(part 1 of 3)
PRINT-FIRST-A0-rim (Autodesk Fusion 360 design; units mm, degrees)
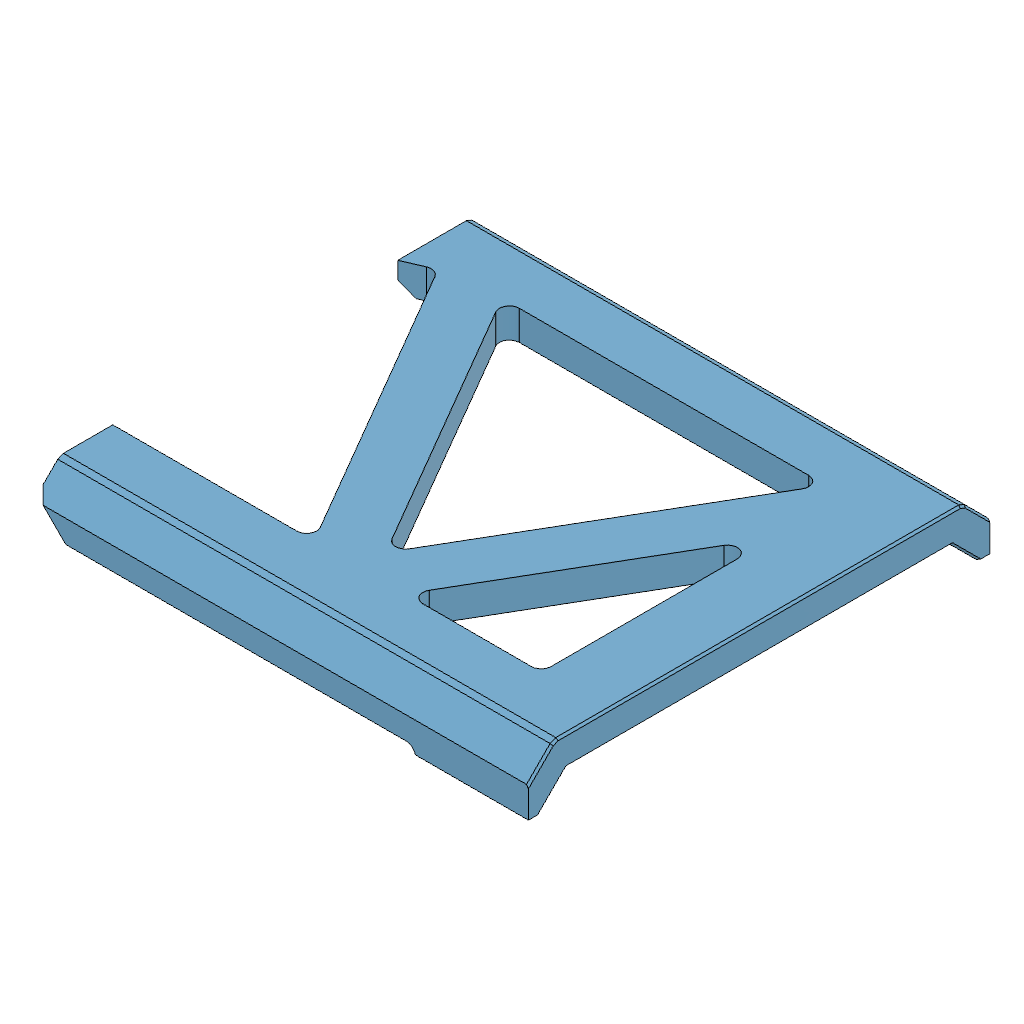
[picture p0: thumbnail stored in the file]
part number: 2026-11-02-20-17-55-344
part number: 2026-11-02-20-17-59-218
part number: 2026-11-02-20-17-59-224
part number: 2026-11-02-20-19-00-695
part number: 2026-11-02-20-19-03-009
part number: 2026-11-02-20-19-04-949
part number: 2026-11-02-20-19-06-912
part number: 2026-11-02-20-19-11-903
part number: 2026-11-02-20-19-12-666
part number: 2026-11-02-20-19-12-978
part number: 2026-11-02-20-19-13-740
part number: 2026-11-02-20-19-14-532
part number: 2026-11-02-20-19-15-361
part number: 2026-11-02-20-19-17-468
part number: 2026-11-02-20-19-19-583
part number: 2026-11-02-20-19-25-638
part number: 2026-11-02-20-19-39-091
parameter "bodyWidth" = 150 comment "Regular octagon across flats; corner diameter is larger."
parameter "bodyLength" = 260 comment "Overall straight length of the shared master blank."
parameter "splitAngle" = 45 comment "Keep this lesson angle at45 degrees."
parameter "faceGap" = 1 comment "Gap between the two printed joint faces."
parameter "wall" = 4.5 comment "Integrated shell and side brace radial thickness."
parameter "faceHalfWidth" = 31.066 (= "bodyWidth * ( sqrt(2) - 1 ) / 2") comment "Half-width of each outer planar facet."
parameter "memberWidth" = 8 comment "Nominal brace and corner chord width in a facet."
parameter "nodeHalfWidth" = 27.066 (= "faceHalfWidth - memberWidth / 2") comment "Chord centerlines measured from facet center."
parameter "jointNodeQ" = 7 comment "First truss skeleton row from the center joint plane."
parameter "endRim" = 10 comment "Uncut axial rim at each distant end."
parameter "endNodeX" = 124 (= "bodyLength / 2 - endRim + memberWidth / 2") comment "Last skeleton row before aperture inset."
parameter "apertureRadius" = 1.5 comment "Rounded internal corners at triangular openings."
parameter "spokeWidth" = 10 comment "Width of each deep bearing bulkhead spoke."
parameter "spokeDepth" = 18 comment "Bulkhead depth normal to the diagonal joint face."
parameter "carrierOD" = 52 comment "Outside of integrated A front bearing carrier."
parameter "rearCarrierClearance" = 46 comment "Internal carrier relief above front bearing shoulder."
parameter "tubeCornerChamfer" = 0.5 comment "Exposed outside octagon corner bevel."
parameter "tubeRimChamfer" = 0.3 comment "End rim and print-contact edge relief."
parameter "cordStation" = 125 (= "bodyLength / 2 - endRim / 2") comment "Load-test cord port center measured along body X."
parameter "bearingOD" = 22 comment "608 measured outside diameter."
parameter "bearingID" = 8 comment "608 bore."
parameter "bearingWidth" = 7 comment "608 width."
parameter "seatAllowance" = 0.2 comment "Trial DIAMETRAL clearance; choose with printed coupon."
parameter "seatDiameter" = 22.2 (= "bearingOD + seatAllowance") comment "Measured fit controls this."
parameter "coreOD" = 44 comment "Bearing holder outer diameter."
parameter "raceRelief" = 19.5 comment "Outer-ring shoulder opening; verify seals."
parameter "frontSeatDepth" = 7.1 comment "0.1 mm outer-ring axial allowance."
parameter "rearSeatDepth" = 7.2 comment "0.2 mm outer-ring axial float."
parameter "shoulder" = 3 comment "Backing behind each bearing seat."
parameter "supportSpacer" = 12 comment "Purchased metal M3 spacer length."
parameter "supportCircle" = 34 comment "Three M3 support bolts."
parameter "supportSpacerOD" = 6 comment "Purchased spacer outside diameter."
parameter "capThickness" = 3 comment "Both printed outer-ring retaining caps."
parameter "m3Clearance" = 3.3 comment "M3 through holes."
parameter "m4Clearance" = 4.3 comment "M4 through holes."
parameter "qFront" = 0.5 (= "faceGap / 2") comment "Front bearing starts at A mating face."
parameter "qFrontBack" = 10.6 (= "qFront + frontSeatDepth + shoulder") comment "End of integrated A holder."
parameter "qRearBase" = 22.6 (= "qFrontBack + supportSpacer") comment "Start of removable rear holder."
parameter "qRearBearing" = 25.6 (= "qRearBase + shoulder") comment "Rear bearing inner end."
parameter "qRearEnd" = 32.8 (= "qRearBearing + rearSeatDepth") comment "Rear holder outer end."
parameter "bearingSpacing" = 25.1 (= "qRearBearing - qFront") comment "Derived support-center spacing, not a bearing rating."
parameter "mountOD" = 76 comment "B mount and F flange outside diameter."
parameter "mountCircle" = 64 comment "Four M4 attachment holes."
parameter "mountOpening" = 50.3 comment "B through opening."
parameter "hubFace" = -23 comment "Metal hub flat mounting face."
parameter "adapterThickness" = 6 comment "F flange and metal compression sleeve length."
parameter "pilotDiameter" = 50 comment "F shallow centering pilot."
parameter "pilotInside" = 34 comment "Clearance around metal hub."
parameter "pilotHeight" = 2 comment "Short pilot only."
parameter "hubHoleSpacing" = 16 comment "Metal Sonic hub square hole spacing."
parameter "sleeveOD" = 8 comment "M4 metal compression sleeves."
parameter "sleeveAllowance" = 0.2 comment "Trial DIAMETRAL sleeve clearance."
parameter "shaftClearance" = 8.5 comment "F clearance hole; not a bearing."
parameter "nutAF" = 7.2 comment "M4 nominal 7 AF nut trial pocket."
parameter "nutDepth" = 4 comment "Open front M4 nut pocket."
parameter "rootRadius" = 1 comment "Hub-to-wall blend."
parameter "entryChamfer" = 0.4 comment "Assembly lead-in."
parameter "bedRelief" = 0.3 comment "Bed-contact edge allowance."
parameter "driverPort" = 5 comment "Clearance for bare3 mm hex-key shafts; bulky bit holders do not fit."
parameter "accessPadWidth" = 12 comment "Reinforced access-port capsule width."
parameter "accessPadExtra" = 2 comment "Local inward reinforcement beyond nominal side wall."
sketch "01 Master Octagon" plane through (0, 0, 0) normal (1, 0, 0) x axis (0, 0, -1)
  line L1 (31.066, 75) -> (75, 31.066)
  line L2 (-31.066, 75) -> (31.066, 75)
  line L3 (-75, 31.066) -> (-31.066, 75)
  line L4 (-75, -31.066) -> (-75, 31.066)
  line L5 (-31.066, -75) -> (-75, -31.066)
  line L6 (31.066, -75) -> (-31.066, -75)
  line L7 (75, -31.066) -> (31.066, -75)
  line L8 (75, 31.066) -> (75, -31.066)
  point P1 (0, 0)
  point P10 (0, 0)
  point P3 (31.066, 75)
  point P8 (31.066, -75)
  coincident P1 P10
  horizontal L2
  dimension "d59" distance P3 P8 = 150 (= "bodyWidth")
extrude "Extrude1" new body sketch "01 Master Octagon" distance 260 (= "bodyLength")
work_plane "WorkPlane1" RotateAngle 45 (= "splitAngle") ExtraOffset 0
split "Split1"
offset_faces "OffsetFaces1" distance -0.5 (= "-faceGap / 2")
offset_faces "OffsetFaces2" distance -0.5 (= "-faceGap / 2")
component_from_bodies "Body->Comp1"
component_from_bodies "Body->Comp2"
shell "Shell1" innerThickness 4.5 (= "wall")
shell "Shell1" innerThickness 4.5 (= "wall")
work_plane "WorkPlane1" RotateAngle -90 ExtraOffset 0
work_plane "WorkPlane2" AlongDistance 75 (= "bodyWidth / 2") ExtraOffset 0
sketch "A Facet 0 Triangle 1" plane through (0, 75, 0) normal (0, 1, 0) x axis (1, 0, 0)
  line L1 (-65.1005, -27.066) -> (-65.1005, 27.066)
  line L2 (60.9665, 27.066) -> (-65.1005, -27.066)
  line L3 (-65.1005, 27.066) -> (60.9665, 27.066)
  line L4 (-61.1005, -20.9953) -> (-61.1005, 23.066)
  line L5 (41.513, 23.066) -> (-61.1005, -20.9953)
  line L6 (-61.1005, 23.066) -> (41.513, 23.066)
  point P1 (0, 0)
  point P2 (-65.1005, 27.066)
  point P3 (-65.1005, -27.066)
  point P4 (60.9665, 27.066)
  dimension "d72" distance P1 P2 = 65.1005 (= "Linear Dimension-2")
  dimension "d73" distance P1 P2 = 27.066 (= "Linear Dimension-3")
  dimension "d74" distance P1 P3 = 65.1005 (= "Linear Dimension-4")
  dimension "d75" distance P1 P3 = 27.066 (= "Linear Dimension-5")
  dimension "d76" distance P1 P4 = 60.9665 (= "Linear Dimension-6")
  dimension "d77" distance P1 P4 = 27.066 (= "Linear Dimension-7")
  dimension "d78" = -4 (= "-memberWidth / 2")
extrude "Extrude1" cut sketch "A Facet 0 Triangle 1" profile of L5 L6 L4 against normal blind 4.7 (magnitude of "-( wall + 0.2 mm )")
sketch "A Facet 0 Triangle 2" plane through (0, 75, 0) normal (0, 1, 0) x axis (1, 0, 0)
  line L1 (60.9665, 27.066) -> (-65.1005, -27.066)
  line L2 (92.4832, -27.066) -> (60.9665, 27.066)
  line L3 (-65.1005, -27.066) -> (92.4832, -27.066)
  line L4 (59.2912, 21.9935) -> (-45.647, -23.066)
  line L5 (85.5258, -23.066) -> (59.2912, 21.9935)
  line L6 (-45.647, -23.066) -> (85.5258, -23.066)
  point P1 (0, 0)
  point P2 (-65.1005, -27.066)
  point P3 (60.9665, 27.066)
  point P4 (92.4832, -27.066)
  dimension "d81" distance P1 P2 = 65.1005 (= "Linear Dimension-2")
  dimension "d82" distance P1 P2 = 27.066 (= "Linear Dimension-3")
  dimension "d83" distance P1 P3 = 60.9665 (= "Linear Dimension-4")
  dimension "d84" distance P1 P3 = 27.066 (= "Linear Dimension-5")
  dimension "d85" distance P1 P4 = 92.4832 (= "Linear Dimension-6")
  dimension "d86" distance P1 P4 = 27.066 (= "Linear Dimension-7")
  dimension "d87" = 4 (= "memberWidth / 2")
extrude "Extrude2" cut sketch "A Facet 0 Triangle 2" profile of L5 L6 L4 against normal blind 4.7 (magnitude of "-( wall + 0.2 mm )")
sketch "A Facet 0 Triangle 3" plane through (0, 75, 0) normal (0, 1, 0) x axis (1, 0, 0)
  line L1 (92.4832, -27.066) -> (60.9665, 27.066)
  line L2 (124, 27.066) -> (92.4832, -27.066)
  line L3 (60.9665, 27.066) -> (124, 27.066)
  line L4 (92.4832, -19.1161) -> (67.924, 23.066)
  line L5 (117.0425, 23.066) -> (92.4832, -19.1161)
  line L6 (67.924, 23.066) -> (117.0425, 23.066)
  point P1 (0, 0)
  point P2 (60.9665, 27.066)
  point P3 (92.4832, -27.066)
  point P4 (124, 27.066)
  dimension "d90" distance P1 P2 = 60.9665 (= "Linear Dimension-2")
  dimension "d91" distance P1 P2 = 27.066 (= "Linear Dimension-3")
  dimension "d92" distance P1 P3 = 92.4832 (= "Linear Dimension-4")
  dimension "d93" distance P1 P3 = 27.066 (= "Linear Dimension-5")
  dimension "d94" distance P1 P4 = 124 (= "Linear Dimension-6")
  dimension "d95" distance P1 P4 = 27.066 (= "Linear Dimension-7")
  dimension "d96" = -4 (= "-memberWidth / 2")
extrude "Extrude3" cut sketch "A Facet 0 Triangle 3" profile of L5 L6 L4 against normal blind 4.7 (magnitude of "-( wall + 0.2 mm )")
sketch "A Facet 0 Triangle 4" plane through (0, 75, 0) normal (0, 1, 0) x axis (1, 0, 0)
  line L1 (124, 27.066) -> (92.4832, -27.066)
  line L2 (124, -27.066) -> (124, 27.066)
  line L3 (92.4832, -27.066) -> (124, -27.066)
  line L4 (120, 12.2459) -> (99.4407, -23.066)
  line L5 (120, -23.066) -> (120, 12.2459)
  line L6 (99.4407, -23.066) -> (120, -23.066)
  point P1 (0, 0)
  point P2 (92.4832, -27.066)
  point P3 (124, 27.066)
  point P4 (124, -27.066)
  dimension "d99" distance P1 P2 = 92.4832 (= "Linear Dimension-2")
  dimension "d100" distance P1 P2 = 27.066 (= "Linear Dimension-3")
  dimension "d101" distance P1 P3 = 124 (= "Linear Dimension-4")
  dimension "d102" distance P1 P3 = 27.066 (= "Linear Dimension-5")
  dimension "d103" distance P1 P4 = 124 (= "Linear Dimension-6")
  dimension "d104" distance P1 P4 = 27.066 (= "Linear Dimension-7")
  dimension "d105" = 4 (= "memberWidth / 2")
extrude "Extrude4" cut sketch "A Facet 0 Triangle 4" profile of L5 L6 L4 against normal blind 4.7 (magnitude of "-( wall + 0.2 mm )")
fillet "Fillet1" radius 1.5 (= "apertureRadius")
work_plane "WorkPlane3" RotateAngle -45 ExtraOffset 0
work_plane "WorkPlane4" AlongDistance 75 (= "bodyWidth / 2") ExtraOffset 0
sketch "A Facet 45 Triangle 1" plane through (0, 53.033, 53.033) normal (0, 0.7071, 0.7071) x axis (1, 0, 0)
  line L1 (-23.9949, -27.066) -> (-62.2721, 27.066)
  line L2 (-0.1814, 27.066) -> (-23.9949, -27.066)
  line L3 (-62.2721, 27.066) -> (-0.1814, 27.066)
  line L4 (-24.81, -18.9852) -> (-54.5447, 23.066)
  line L5 (-6.311, 23.066) -> (-24.81, -18.9852)
  line L6 (-54.5447, 23.066) -> (-6.311, 23.066)
  point P1 (0, 0)
  point P2 (-62.2721, 27.066)
  point P3 (-23.9949, -27.066)
  point P4 (-0.1814, 27.066)
  dimension "d114" distance P1 P2 = 62.2721 (= "Linear Dimension-2")
  dimension "d115" distance P1 P2 = 27.066 (= "Linear Dimension-3")
  dimension "d116" distance P1 P3 = 23.9949 (= "Linear Dimension-4")
  dimension "d117" distance P1 P3 = 27.066 (= "Linear Dimension-5")
  dimension "d118" distance P1 P4 = 0.1814 (= "Linear Dimension-6")
  dimension "d119" distance P1 P4 = 27.066 (= "Linear Dimension-7")
  dimension "d120" = -4 (= "-memberWidth / 2")
extrude "Extrude5" cut sketch "A Facet 45 Triangle 1" profile of L5 L6 L4 against normal blind 4.7 (magnitude of "-( wall + 0.2 mm )")
sketch "A Facet 45 Triangle 2" plane through (0, 53.033, 53.033) normal (0, 0.7071, 0.7071) x axis (1, 0, 0)
  line L1 (-0.1814, 27.066) -> (-23.9949, -27.066)
  line L2 (74.6684, -27.066) -> (-0.1814, 27.066)
  line L3 (-23.9949, -27.066) -> (74.6684, -27.066)
  line L4 (1.4863, 20.9235) -> (-17.8653, -23.066)
  line L5 (62.3117, -23.066) -> (1.4863, 20.9235)
  line L6 (-17.8653, -23.066) -> (62.3117, -23.066)
  point P1 (0, 0)
  point P2 (-23.9949, -27.066)
  point P3 (-0.1814, 27.066)
  point P4 (74.6684, -27.066)
  dimension "d123" distance P1 P2 = 23.9949 (= "Linear Dimension-2")
  dimension "d124" distance P1 P2 = 27.066 (= "Linear Dimension-3")
  dimension "d125" distance P1 P3 = 0.1814 (= "Linear Dimension-4")
  dimension "d126" distance P1 P3 = 27.066 (= "Linear Dimension-5")
  dimension "d127" distance P1 P4 = 74.6684 (= "Linear Dimension-6")
  dimension "d128" distance P1 P4 = 27.066 (= "Linear Dimension-7")
  dimension "d129" = 4 (= "memberWidth / 2")
extrude "Extrude6" cut sketch "A Facet 45 Triangle 2" profile of L5 L6 L4 against normal blind 4.7 (magnitude of "-( wall + 0.2 mm )")
sketch "A Facet 45 Triangle 3" plane through (0, 53.033, 53.033) normal (0, 0.7071, 0.7071) x axis (1, 0, 0)
  line L1 (74.6684, -27.066) -> (-0.1814, 27.066)
  line L2 (124, 27.066) -> (74.6684, -27.066)
  line L3 (-0.1814, 27.066) -> (124, 27.066)
  line L4 (74.1179, -21.7315) -> (12.1753, 23.066)
  line L5 (114.9429, 23.066) -> (74.1179, -21.7315)
  line L6 (12.1753, 23.066) -> (114.9429, 23.066)
  point P1 (0, 0)
  point P2 (-0.1814, 27.066)
  point P3 (74.6684, -27.066)
  point P4 (124, 27.066)
  dimension "d132" distance P1 P2 = 0.1814 (= "Linear Dimension-2")
  dimension "d133" distance P1 P2 = 27.066 (= "Linear Dimension-3")
  dimension "d134" distance P1 P3 = 74.6684 (= "Linear Dimension-4")
  dimension "d135" distance P1 P3 = 27.066 (= "Linear Dimension-5")
  dimension "d136" distance P1 P4 = 124 (= "Linear Dimension-6")
  dimension "d137" distance P1 P4 = 27.066 (= "Linear Dimension-7")
  dimension "d138" = -4 (= "-memberWidth / 2")
extrude "Extrude7" cut sketch "A Facet 45 Triangle 3" profile of L5 L6 L4 against normal blind 4.7 (magnitude of "-( wall + 0.2 mm )")
sketch "A Facet 45 Triangle 4" plane through (0, 53.033, 53.033) normal (0, 0.7071, 0.7071) x axis (1, 0, 0)
  line L1 (124, 27.066) -> (74.6684, -27.066)
  line L2 (124, -27.066) -> (124, 27.066)
  line L3 (74.6684, -27.066) -> (124, -27.066)
  line L4 (120, 16.7383) -> (83.7255, -23.066)
  line L5 (120, -23.066) -> (120, 16.7383)
  line L6 (83.7255, -23.066) -> (120, -23.066)
  point P1 (0, 0)
  point P2 (74.6684, -27.066)
  point P3 (124, 27.066)
  point P4 (124, -27.066)
  dimension "d141" distance P1 P2 = 74.6684 (= "Linear Dimension-2")
  dimension "d142" distance P1 P2 = 27.066 (= "Linear Dimension-3")
  dimension "d143" distance P1 P3 = 124 (= "Linear Dimension-4")
  dimension "d144" distance P1 P3 = 27.066 (= "Linear Dimension-5")
  dimension "d145" distance P1 P4 = 124 (= "Linear Dimension-6")
  dimension "d146" distance P1 P4 = 27.066 (= "Linear Dimension-7")
  dimension "d147" = 4 (= "memberWidth / 2")
extrude "Extrude8" cut sketch "A Facet 45 Triangle 4" profile of L5 L6 L4 against normal blind 4.7 (magnitude of "-( wall + 0.2 mm )")
fillet "Fillet2" radius 1.5 (= "apertureRadius")
work_plane "WorkPlane5" RotateAngle 0 ExtraOffset 0
work_plane "WorkPlane6" AlongDistance 75 (= "bodyWidth / 2") ExtraOffset 0
sketch "A Facet 90 Triangle 1" plane through (0, 0, 75) normal (0, 0, 1) x axis (1, 0, 0)
  line L1 (36.9655, -27.066) -> (-17.1665, 27.066)
  line L2 (53.4167, 27.066) -> (36.9655, -27.066)
  line L3 (-17.1665, 27.066) -> (53.4167, 27.066)
  line L4 (35.0777, -19.5214) -> (-7.5097, 23.066)
  line L5 (48.0205, 23.066) -> (35.0777, -19.5214)
  line L6 (-7.5097, 23.066) -> (48.0205, 23.066)
  point P1 (0, 0)
  point P2 (-17.1665, 27.066)
  point P3 (36.9655, -27.066)
  point P4 (53.4167, 27.066)
  dimension "d156" distance P1 P2 = 17.1665 (= "Linear Dimension-2")
  dimension "d157" distance P1 P2 = 27.066 (= "Linear Dimension-3")
  dimension "d158" distance P1 P3 = 36.9655 (= "Linear Dimension-4")
  dimension "d159" distance P1 P3 = 27.066 (= "Linear Dimension-5")
  dimension "d160" distance P1 P4 = 53.4167 (= "Linear Dimension-6")
  dimension "d161" distance P1 P4 = 27.066 (= "Linear Dimension-7")
  dimension "d162" = -4 (= "-memberWidth / 2")
extrude "Extrude9" cut sketch "A Facet 90 Triangle 1" profile of L5 L6 L4 against normal blind 4.7 (magnitude of "-( wall + 0.2 mm )")
sketch "A Facet 90 Triangle 2" plane through (0, 0, 75) normal (0, 0, 1) x axis (1, 0, 0)
  line L1 (53.4167, 27.066) -> (36.9655, -27.066)
  line L2 (124, -27.066) -> (53.4167, 27.066)
  line L3 (36.9655, -27.066) -> (124, -27.066)
  line L4 (55.5648, 20.3777) -> (42.3618, -23.066)
  line L5 (112.2115, -23.066) -> (55.5648, 20.3777)
  line L6 (42.3618, -23.066) -> (112.2115, -23.066)
  point P1 (0, 0)
  point P2 (36.9655, -27.066)
  point P3 (53.4167, 27.066)
  point P4 (124, -27.066)
  dimension "d165" distance P1 P2 = 36.9655 (= "Linear Dimension-2")
  dimension "d166" distance P1 P2 = 27.066 (= "Linear Dimension-3")
  dimension "d167" distance P1 P3 = 53.4167 (= "Linear Dimension-4")
  dimension "d168" distance P1 P3 = 27.066 (= "Linear Dimension-5")
  dimension "d169" distance P1 P4 = 124 (= "Linear Dimension-6")
  dimension "d170" distance P1 P4 = 27.066 (= "Linear Dimension-7")
  dimension "d171" = 4 (= "memberWidth / 2")
extrude "Extrude10" cut sketch "A Facet 90 Triangle 2" profile of L5 L6 L4 against normal blind 4.7 (magnitude of "-( wall + 0.2 mm )")
sketch "A Facet 90 Triangle 3" plane through (0, 0, 75) normal (0, 0, 1) x axis (1, 0, 0)
  line L1 (124, -27.066) -> (53.4167, 27.066)
  line L2 (124, 27.066) -> (124, -27.066)
  line L3 (53.4167, 27.066) -> (124, 27.066)
  line L4 (120, -18.9574) -> (65.2053, 23.066)
  line L5 (120, 23.066) -> (120, -18.9574)
  line L6 (65.2053, 23.066) -> (120, 23.066)
  point P1 (0, 0)
  point P2 (53.4167, 27.066)
  point P3 (124, -27.066)
  point P4 (124, 27.066)
  dimension "d174" distance P1 P2 = 53.4167 (= "Linear Dimension-2")
  dimension "d175" distance P1 P2 = 27.066 (= "Linear Dimension-3")
  dimension "d176" distance P1 P3 = 124 (= "Linear Dimension-4")
  dimension "d177" distance P1 P3 = 27.066 (= "Linear Dimension-5")
  dimension "d178" distance P1 P4 = 124 (= "Linear Dimension-6")
  dimension "d179" distance P1 P4 = 27.066 (= "Linear Dimension-7")
  dimension "d180" = -4 (= "-memberWidth / 2")
extrude "Extrude11" cut sketch "A Facet 90 Triangle 3" profile of L5 L6 L4 against normal blind 4.7 (magnitude of "-( wall + 0.2 mm )")
fillet "Fillet3" radius 1.5 (= "apertureRadius")
work_plane "WorkPlane7" RotateAngle 45 ExtraOffset 0
work_plane "WorkPlane8" AlongDistance 75 (= "bodyWidth / 2") ExtraOffset 0
sketch "A Facet 135 Triangle 1" plane through (0, -53.033, 53.033) normal (0, -0.7071, 0.7071) x axis (1, 0, 0)
  line L1 (82.0711, -27.066) -> (43.7939, 27.066)
  line L2 (124, 27.066) -> (82.0711, -27.066)
  line L3 (43.7939, 27.066) -> (124, 27.066)
  line L4 (82.2175, -20.3449) -> (51.5213, 23.066)
  line L5 (115.8422, 23.066) -> (82.2175, -20.3449)
  line L6 (51.5213, 23.066) -> (115.8422, 23.066)
  point P1 (0, 0)
  point P2 (43.7939, 27.066)
  point P3 (82.0711, -27.066)
  point P4 (124, 27.066)
  dimension "d189" distance P1 P2 = 43.7939 (= "Linear Dimension-2")
  dimension "d190" distance P1 P2 = 27.066 (= "Linear Dimension-3")
  dimension "d191" distance P1 P3 = 82.0711 (= "Linear Dimension-4")
  dimension "d192" distance P1 P3 = 27.066 (= "Linear Dimension-5")
  dimension "d193" distance P1 P4 = 124 (= "Linear Dimension-6")
  dimension "d194" distance P1 P4 = 27.066 (= "Linear Dimension-7")
  dimension "d195" = -4 (= "-memberWidth / 2")
extrude "Extrude12" cut sketch "A Facet 135 Triangle 1" profile of L5 L6 L4 against normal blind 4.7 (magnitude of "-( wall + 0.2 mm )")
sketch "A Facet 135 Triangle 2" plane through (0, -53.033, 53.033) normal (0, -0.7071, 0.7071) x axis (1, 0, 0)
  line L1 (124, 27.066) -> (82.0711, -27.066)
  line L2 (124, -27.066) -> (124, 27.066)
  line L3 (82.0711, -27.066) -> (124, -27.066)
  line L4 (120, 15.3697) -> (90.2289, -23.066)
  line L5 (120, -23.066) -> (120, 15.3697)
  line L6 (90.2289, -23.066) -> (120, -23.066)
  point P1 (0, 0)
  point P2 (82.0711, -27.066)
  point P3 (124, 27.066)
  point P4 (124, -27.066)
  dimension "d198" distance P1 P2 = 82.0711 (= "Linear Dimension-2")
  dimension "d199" distance P1 P2 = 27.066 (= "Linear Dimension-3")
  dimension "d200" distance P1 P3 = 124 (= "Linear Dimension-4")
  dimension "d201" distance P1 P3 = 27.066 (= "Linear Dimension-5")
  dimension "d202" distance P1 P4 = 124 (= "Linear Dimension-6")
  dimension "d203" distance P1 P4 = 27.066 (= "Linear Dimension-7")
  dimension "d204" = 4 (= "memberWidth / 2")
extrude "Extrude13" cut sketch "A Facet 135 Triangle 2" profile of L5 L6 L4 against normal blind 4.7 (magnitude of "-( wall + 0.2 mm )")
fillet "Fillet4" radius 1.5 (= "apertureRadius")
work_plane "WorkPlane9" RotateAngle 90 ExtraOffset 0
work_plane "WorkPlane10" AlongDistance 75 (= "bodyWidth / 2") ExtraOffset 0
sketch "A Facet 180 Triangle 1" plane through (0, -75, 0) normal (0, -1, 0) x axis (-1, 0, 0)
  line L1 (-84.8995, 27.066) -> (-84.8995, -27.066)
  line L2 (-124, -27.066) -> (-84.8995, 27.066)
  line L3 (-84.8995, -27.066) -> (-124, -27.066)
  line L4 (-88.8995, 14.697) -> (-88.8995, -23.066)
  line L5 (-116.1764, -23.066) -> (-88.8995, 14.697)
  line L6 (-88.8995, -23.066) -> (-116.1764, -23.066)
  point P1 (0, 0)
  point P2 (-84.8995, -27.066)
  point P3 (-84.8995, 27.066)
  point P4 (-124, -27.066)
  dimension "d213" distance P1 P2 = 84.8995 (= "Linear Dimension-2")
  dimension "d214" distance P1 P2 = 27.066 (= "Linear Dimension-3")
  dimension "d215" distance P1 P3 = 84.8995 (= "Linear Dimension-4")
  dimension "d216" distance P1 P3 = 27.066 (= "Linear Dimension-5")
  dimension "d217" distance P1 P4 = 124 (= "Linear Dimension-6")
  dimension "d218" distance P1 P4 = 27.066 (= "Linear Dimension-7")
  dimension "d219" = -4 (= "-memberWidth / 2")
extrude "Extrude14" cut sketch "A Facet 180 Triangle 1" profile of L5 L6 L4 against normal blind 4.7 (magnitude of "-( wall + 0.2 mm )")
sketch "A Facet 180 Triangle 2" plane through (0, -75, 0) normal (0, -1, 0) x axis (-1, 0, 0)
  line L1 (-124, -27.066) -> (-84.8995, 27.066)
  line L2 (-124, 27.066) -> (-124, -27.066)
  line L3 (-84.8995, 27.066) -> (-124, 27.066)
  line L4 (-120, -14.697) -> (-92.7231, 23.066)
  line L5 (-120, 23.066) -> (-120, -14.697)
  line L6 (-92.7231, 23.066) -> (-120, 23.066)
  point P1 (0, 0)
  point P2 (-84.8995, 27.066)
  point P3 (-124, -27.066)
  point P4 (-124, 27.066)
  dimension "d222" distance P1 P2 = 84.8995 (= "Linear Dimension-2")
  dimension "d223" distance P1 P2 = 27.066 (= "Linear Dimension-3")
  dimension "d224" distance P1 P3 = 124 (= "Linear Dimension-4")
  dimension "d225" distance P1 P3 = 27.066 (= "Linear Dimension-5")
  dimension "d226" distance P1 P4 = 124 (= "Linear Dimension-6")
  dimension "d227" distance P1 P4 = 27.066 (= "Linear Dimension-7")
  dimension "d228" = 4 (= "memberWidth / 2")
extrude "Extrude15" cut sketch "A Facet 180 Triangle 2" profile of L5 L6 L4 against normal blind 4.7 (magnitude of "-( wall + 0.2 mm )")
fillet "Fillet5" radius 1.5 (= "apertureRadius")
work_plane "WorkPlane11" RotateAngle 135 ExtraOffset 0
work_plane "WorkPlane12" AlongDistance 75 (= "bodyWidth / 2") ExtraOffset 0
sketch "A Facet 225 Triangle 1" plane through (0, -53.033, -53.033) normal (0, -0.7071, -0.7071) x axis (1, 0, 0)
  line L1 (43.7939, -27.066) -> (82.0711, 27.066)
  line L2 (124, 27.066) -> (43.7939, -27.066)
  line L3 (82.0711, 27.066) -> (124, 27.066)
  line L4 (59.6927, -11.51) -> (84.1416, 23.066)
  line L5 (110.9231, 23.066) -> (59.6927, -11.51)
  line L6 (84.1416, 23.066) -> (110.9231, 23.066)
  point P1 (0, 0)
  point P2 (82.0711, 27.066)
  point P3 (43.7939, -27.066)
  point P4 (124, 27.066)
  dimension "d237" distance P1 P2 = 82.0711 (= "Linear Dimension-2")
  dimension "d238" distance P1 P2 = 27.066 (= "Linear Dimension-3")
  dimension "d239" distance P1 P3 = 43.7939 (= "Linear Dimension-4")
  dimension "d240" distance P1 P3 = 27.066 (= "Linear Dimension-5")
  dimension "d241" distance P1 P4 = 124 (= "Linear Dimension-6")
  dimension "d242" distance P1 P4 = 27.066 (= "Linear Dimension-7")
  dimension "d243" = -4 (= "-memberWidth / 2")
extrude "Extrude16" cut sketch "A Facet 225 Triangle 1" profile of L5 L6 L4 against normal blind 4.7 (magnitude of "-( wall + 0.2 mm )")
sketch "A Facet 225 Triangle 2" plane through (0, -53.033, -53.033) normal (0, -0.7071, -0.7071) x axis (1, 0, 0)
  line L1 (124, 27.066) -> (43.7939, -27.066)
  line L2 (124, -27.066) -> (124, 27.066)
  line L3 (43.7939, -27.066) -> (124, -27.066)
  line L4 (120, 19.5406) -> (56.8709, -23.066)
  line L5 (120, -23.066) -> (120, 19.5406)
  line L6 (56.8709, -23.066) -> (120, -23.066)
  point P1 (0, 0)
  point P2 (43.7939, -27.066)
  point P3 (124, 27.066)
  point P4 (124, -27.066)
  dimension "d246" distance P1 P2 = 43.7939 (= "Linear Dimension-2")
  dimension "d247" distance P1 P2 = 27.066 (= "Linear Dimension-3")
  dimension "d248" distance P1 P3 = 124 (= "Linear Dimension-4")
  dimension "d249" distance P1 P3 = 27.066 (= "Linear Dimension-5")
  dimension "d250" distance P1 P4 = 124 (= "Linear Dimension-6")
  dimension "d251" distance P1 P4 = 27.066 (= "Linear Dimension-7")
  dimension "d252" = 4 (= "memberWidth / 2")
extrude "Extrude17" cut sketch "A Facet 225 Triangle 2" profile of L5 L6 L4 against normal blind 4.7 (magnitude of "-( wall + 0.2 mm )")
fillet "Fillet6" radius 1.5 (= "apertureRadius")
work_plane "WorkPlane13" RotateAngle 180 ExtraOffset 0
work_plane "WorkPlane14" AlongDistance 75 (= "bodyWidth / 2") ExtraOffset 0
sketch "A Facet 270 Triangle 1" plane through (0, 0, -75) normal (0, 0, -1) x axis (-1, 0, 0)
  line L1 (17.1665, 27.066) -> (-36.9655, -27.066)
  line L2 (-80.4828, -27.066) -> (17.1665, 27.066)
  line L3 (-36.9655, -27.066) -> (-80.4828, -27.066)
  line L4 (-5.7896, 9.7668) -> (-38.6224, -23.066)
  line L5 (-65.0169, -23.066) -> (-5.7896, 9.7668)
  line L6 (-38.6224, -23.066) -> (-65.0169, -23.066)
  point P1 (0, 0)
  point P2 (-36.9655, -27.066)
  point P3 (17.1665, 27.066)
  point P4 (-80.4828, -27.066)
  dimension "d261" distance P1 P2 = 36.9655 (= "Linear Dimension-2")
  dimension "d262" distance P1 P2 = 27.066 (= "Linear Dimension-3")
  dimension "d263" distance P1 P3 = 17.1665 (= "Linear Dimension-4")
  dimension "d264" distance P1 P3 = 27.066 (= "Linear Dimension-5")
  dimension "d265" distance P1 P4 = 80.4828 (= "Linear Dimension-6")
  dimension "d266" distance P1 P4 = 27.066 (= "Linear Dimension-7")
  dimension "d267" = -4 (= "-memberWidth / 2")
extrude "Extrude18" cut sketch "A Facet 270 Triangle 1" profile of L5 L6 L4 against normal blind 4.7 (magnitude of "-( wall + 0.2 mm )")
sketch "A Facet 270 Triangle 2" plane through (0, 0, -75) normal (0, 0, -1) x axis (-1, 0, 0)
  line L1 (-80.4828, -27.066) -> (17.1665, 27.066)
  line L2 (-124, 27.066) -> (-80.4828, -27.066)
  line L3 (17.1665, 27.066) -> (-124, 27.066)
  line L4 (-79.4759, -21.9343) -> (1.7007, 23.066)
  line L5 (-115.6521, 23.066) -> (-79.4759, -21.9343)
  line L6 (1.7007, 23.066) -> (-115.6521, 23.066)
  point P1 (0, 0)
  point P2 (17.1665, 27.066)
  point P3 (-80.4828, -27.066)
  point P4 (-124, 27.066)
  dimension "d270" distance P1 P2 = 17.1665 (= "Linear Dimension-2")
  dimension "d271" distance P1 P2 = 27.066 (= "Linear Dimension-3")
  dimension "d272" distance P1 P3 = 80.4828 (= "Linear Dimension-4")
  dimension "d273" distance P1 P3 = 27.066 (= "Linear Dimension-5")
  dimension "d274" distance P1 P4 = 124 (= "Linear Dimension-6")
  dimension "d275" distance P1 P4 = 27.066 (= "Linear Dimension-7")
  dimension "d276" = 4 (= "memberWidth / 2")
extrude "Extrude19" cut sketch "A Facet 270 Triangle 2" profile of L5 L6 L4 against normal blind 4.7 (magnitude of "-( wall + 0.2 mm )")
sketch "A Facet 270 Triangle 3" plane through (0, 0, -75) normal (0, 0, -1) x axis (-1, 0, 0)
  line L1 (-124, 27.066) -> (-80.4828, -27.066)
  line L2 (-124, -27.066) -> (-124, 27.066)
  line L3 (-80.4828, -27.066) -> (-124, -27.066)
  line L4 (-120, 15.7062) -> (-88.8307, -23.066)
  line L5 (-120, -23.066) -> (-120, 15.7062)
  line L6 (-88.8307, -23.066) -> (-120, -23.066)
  point P1 (0, 0)
  point P2 (-80.4828, -27.066)
  point P3 (-124, 27.066)
  point P4 (-124, -27.066)
  dimension "d279" distance P1 P2 = 80.4828 (= "Linear Dimension-2")
  dimension "d280" distance P1 P2 = 27.066 (= "Linear Dimension-3")
  dimension "d281" distance P1 P3 = 124 (= "Linear Dimension-4")
  dimension "d282" distance P1 P3 = 27.066 (= "Linear Dimension-5")
  dimension "d283" distance P1 P4 = 124 (= "Linear Dimension-6")
  dimension "d284" distance P1 P4 = 27.066 (= "Linear Dimension-7")
  dimension "d285" = -4 (= "-memberWidth / 2")
extrude "Extrude20" cut sketch "A Facet 270 Triangle 3" profile of L5 L6 L4 against normal blind 4.7 (magnitude of "-( wall + 0.2 mm )")
fillet "Fillet7" radius 1.5 (= "apertureRadius")
work_plane "WorkPlane15" RotateAngle 225 ExtraOffset 0
work_plane "WorkPlane16" AlongDistance 75 (= "bodyWidth / 2") ExtraOffset 0
sketch "A Facet 315 Triangle 1" plane through (0, 53.033, -53.033) normal (0, 0.7071, -0.7071) x axis (1, 0, 0)
  line L1 (-62.2721, -27.066) -> (-23.9949, 27.066)
  line L2 (25.3367, 27.066) -> (-62.2721, -27.066)
  line L3 (-23.9949, 27.066) -> (25.3367, 27.066)
  line L4 (-47.6674, -13.34) -> (-21.9244, 23.066)
  line L5 (11.2532, 23.066) -> (-47.6674, -13.34)
  line L6 (-21.9244, 23.066) -> (11.2532, 23.066)
  point P1 (0, 0)
  point P2 (-23.9949, 27.066)
  point P3 (-62.2721, -27.066)
  point P4 (25.3367, 27.066)
  dimension "d294" distance P1 P2 = 23.9949 (= "Linear Dimension-2")
  dimension "d295" distance P1 P2 = 27.066 (= "Linear Dimension-3")
  dimension "d296" distance P1 P3 = 62.2721 (= "Linear Dimension-4")
  dimension "d297" distance P1 P3 = 27.066 (= "Linear Dimension-5")
  dimension "d298" distance P1 P4 = 25.3367 (= "Linear Dimension-6")
  dimension "d299" distance P1 P4 = 27.066 (= "Linear Dimension-7")
  dimension "d300" = -4 (= "-memberWidth / 2")
extrude "Extrude21" cut sketch "A Facet 315 Triangle 1" profile of L5 L6 L4 against normal blind 4.7 (magnitude of "-( wall + 0.2 mm )")
sketch "A Facet 315 Triangle 2" plane through (0, 53.033, -53.033) normal (0, 0.7071, -0.7071) x axis (1, 0, 0)
  line L1 (25.3367, 27.066) -> (-62.2721, -27.066)
  line L2 (61.9093, -27.066) -> (25.3367, 27.066)
  line L3 (-62.2721, -27.066) -> (61.9093, -27.066)
  line L4 (24.1722, 21.6445) -> (-48.1886, -23.066)
  line L5 (54.3795, -23.066) -> (24.1722, 21.6445)
  line L6 (-48.1886, -23.066) -> (54.3795, -23.066)
  point P1 (0, 0)
  point P2 (-62.2721, -27.066)
  point P3 (25.3367, 27.066)
  point P4 (61.9093, -27.066)
  dimension "d303" distance P1 P2 = 62.2721 (= "Linear Dimension-2")
  dimension "d304" distance P1 P2 = 27.066 (= "Linear Dimension-3")
  dimension "d305" distance P1 P3 = 25.3367 (= "Linear Dimension-4")
  dimension "d306" distance P1 P3 = 27.066 (= "Linear Dimension-5")
  dimension "d307" distance P1 P4 = 61.9093 (= "Linear Dimension-6")
  dimension "d308" distance P1 P4 = 27.066 (= "Linear Dimension-7")
  dimension "d309" = 4 (= "memberWidth / 2")
extrude "Extrude22" cut sketch "A Facet 315 Triangle 2" profile of L5 L6 L4 against normal blind 4.7 (magnitude of "-( wall + 0.2 mm )")
sketch "A Facet 315 Triangle 3" plane through (0, 53.033, -53.033) normal (0, 0.7071, -0.7071) x axis (1, 0, 0)
  line L1 (61.9093, -27.066) -> (25.3367, 27.066)
  line L2 (124, 27.066) -> (61.9093, -27.066)
  line L3 (25.3367, 27.066) -> (124, 27.066)
  line L4 (62.6909, -21.0779) -> (32.8665, 23.066)
  line L5 (113.325, 23.066) -> (62.6909, -21.0779)
  line L6 (32.8665, 23.066) -> (113.325, 23.066)
  point P1 (0, 0)
  point P2 (25.3367, 27.066)
  point P3 (61.9093, -27.066)
  point P4 (124, 27.066)
  dimension "d312" distance P1 P2 = 25.3367 (= "Linear Dimension-2")
  dimension "d313" distance P1 P2 = 27.066 (= "Linear Dimension-3")
  dimension "d314" distance P1 P3 = 61.9093 (= "Linear Dimension-4")
  dimension "d315" distance P1 P3 = 27.066 (= "Linear Dimension-5")
  dimension "d316" distance P1 P4 = 124 (= "Linear Dimension-6")
  dimension "d317" distance P1 P4 = 27.066 (= "Linear Dimension-7")
  dimension "d318" = -4 (= "-memberWidth / 2")
extrude "Extrude23" cut sketch "A Facet 315 Triangle 3" profile of L5 L6 L4 against normal blind 4.7 (magnitude of "-( wall + 0.2 mm )")
sketch "A Facet 315 Triangle 4" plane through (0, 53.033, -53.033) normal (0, 0.7071, -0.7071) x axis (1, 0, 0)
  line L1 (124, 27.066) -> (61.9093, -27.066)
  line L2 (124, -27.066) -> (124, 27.066)
  line L3 (61.9093, -27.066) -> (124, -27.066)
  line L4 (120, 18.272) -> (72.5843, -23.066)
  line L5 (120, -23.066) -> (120, 18.272)
  line L6 (72.5843, -23.066) -> (120, -23.066)
  point P1 (0, 0)
  point P2 (61.9093, -27.066)
  point P3 (124, 27.066)
  point P4 (124, -27.066)
  dimension "d321" distance P1 P2 = 61.9093 (= "Linear Dimension-2")
  dimension "d322" distance P1 P2 = 27.066 (= "Linear Dimension-3")
  dimension "d323" distance P1 P3 = 124 (= "Linear Dimension-4")
  dimension "d324" distance P1 P3 = 27.066 (= "Linear Dimension-5")
  dimension "d325" distance P1 P4 = 124 (= "Linear Dimension-6")
  dimension "d326" distance P1 P4 = 27.066 (= "Linear Dimension-7")
  dimension "d327" = 4 (= "memberWidth / 2")
extrude "Extrude24" cut sketch "A Facet 315 Triangle 4" profile of L5 L6 L4 against normal blind 4.7 (magnitude of "-( wall + 0.2 mm )")
fillet "Fillet8" radius 1.5 (= "apertureRadius")
work_plane "WorkPlane1" RotateAngle -90 ExtraOffset 0
work_plane "WorkPlane2" AlongDistance 75 (= "bodyWidth / 2") ExtraOffset 0
sketch "B Facet 0 Triangle 1" plane through (0, 75, 0) normal (0, 1, 0) x axis (1, 0, 0)
  line L1 (-84.8995, -27.066) -> (-84.8995, 27.066)
  line L2 (-124, 27.066) -> (-84.8995, -27.066)
  line L3 (-84.8995, 27.066) -> (-124, 27.066)
  line L4 (-88.8995, -14.697) -> (-88.8995, 23.066)
  line L5 (-116.1764, 23.066) -> (-88.8995, -14.697)
  line L6 (-88.8995, 23.066) -> (-116.1764, 23.066)
  point P1 (0, 0)
  point P2 (-84.8995, 27.066)
  point P3 (-84.8995, -27.066)
  point P4 (-124, 27.066)
  dimension "d336" distance P1 P2 = 84.8995 (= "Linear Dimension-2")
  dimension "d337" distance P1 P2 = 27.066 (= "Linear Dimension-3")
  dimension "d338" distance P1 P3 = 84.8995 (= "Linear Dimension-4")
  dimension "d339" distance P1 P3 = 27.066 (= "Linear Dimension-5")
  dimension "d340" distance P1 P4 = 124 (= "Linear Dimension-6")
  dimension "d341" distance P1 P4 = 27.066 (= "Linear Dimension-7")
  dimension "d342" = 4 (= "memberWidth / 2")
extrude "Extrude1" cut sketch "B Facet 0 Triangle 1" profile of L5 L6 L4 against normal blind 4.7 (magnitude of "-( wall + 0.2 mm )")
sketch "B Facet 0 Triangle 2" plane through (0, 75, 0) normal (0, 1, 0) x axis (1, 0, 0)
  line L1 (-124, 27.066) -> (-84.8995, -27.066)
  line L2 (-124, -27.066) -> (-124, 27.066)
  line L3 (-84.8995, -27.066) -> (-124, -27.066)
  line L4 (-120, 14.697) -> (-92.7231, -23.066)
  line L5 (-120, -23.066) -> (-120, 14.697)
  line L6 (-92.7231, -23.066) -> (-120, -23.066)
  point P1 (0, 0)
  point P2 (-84.8995, -27.066)
  point P3 (-124, 27.066)
  point P4 (-124, -27.066)
  dimension "d345" distance P1 P2 = 84.8995 (= "Linear Dimension-2")
  dimension "d346" distance P1 P2 = 27.066 (= "Linear Dimension-3")
  dimension "d347" distance P1 P3 = 124 (= "Linear Dimension-4")
  dimension "d348" distance P1 P3 = 27.066 (= "Linear Dimension-5")
  dimension "d349" distance P1 P4 = 124 (= "Linear Dimension-6")
  dimension "d350" distance P1 P4 = 27.066 (= "Linear Dimension-7")
  dimension "d351" = -4 (= "-memberWidth / 2")
extrude "Extrude2" cut sketch "B Facet 0 Triangle 2" profile of L5 L6 L4 against normal blind 4.7 (magnitude of "-( wall + 0.2 mm )")
fillet "Fillet1" radius 1.5 (= "apertureRadius")
work_plane "WorkPlane3" RotateAngle -45 ExtraOffset 0
work_plane "WorkPlane4" AlongDistance 75 (= "bodyWidth / 2") ExtraOffset 0
sketch "B Facet 45 Triangle 1" plane through (0, 53.033, 53.033) normal (0, 0.7071, 0.7071) x axis (1, 0, 0)
  line L1 (-43.7939, -27.066) -> (-82.0711, 27.066)
  line L2 (-124, 27.066) -> (-43.7939, -27.066)
  line L3 (-82.0711, 27.066) -> (-124, 27.066)
  line L4 (-59.6927, -11.51) -> (-84.1416, 23.066)
  line L5 (-110.9231, 23.066) -> (-59.6927, -11.51)
  line L6 (-84.1416, 23.066) -> (-110.9231, 23.066)
  point P1 (0, 0)
  point P2 (-82.0711, 27.066)
  point P3 (-43.7939, -27.066)
  point P4 (-124, 27.066)
  dimension "d360" distance P1 P2 = 82.0711 (= "Linear Dimension-2")
  dimension "d361" distance P1 P2 = 27.066 (= "Linear Dimension-3")
  dimension "d362" distance P1 P3 = 43.7939 (= "Linear Dimension-4")
  dimension "d363" distance P1 P3 = 27.066 (= "Linear Dimension-5")
  dimension "d364" distance P1 P4 = 124 (= "Linear Dimension-6")
  dimension "d365" distance P1 P4 = 27.066 (= "Linear Dimension-7")
  dimension "d366" = 4 (= "memberWidth / 2")
extrude "Extrude3" cut sketch "B Facet 45 Triangle 1" profile of L5 L6 L4 against normal blind 4.7 (magnitude of "-( wall + 0.2 mm )")
sketch "B Facet 45 Triangle 2" plane through (0, 53.033, 53.033) normal (0, 0.7071, 0.7071) x axis (1, 0, 0)
  line L1 (-124, 27.066) -> (-43.7939, -27.066)
  line L2 (-124, -27.066) -> (-124, 27.066)
  line L3 (-43.7939, -27.066) -> (-124, -27.066)
  line L4 (-120, 19.5406) -> (-56.8709, -23.066)
  line L5 (-120, -23.066) -> (-120, 19.5406)
  line L6 (-56.8709, -23.066) -> (-120, -23.066)
  point P1 (0, 0)
  point P2 (-43.7939, -27.066)
  point P3 (-124, 27.066)
  point P4 (-124, -27.066)
  dimension "d369" distance P1 P2 = 43.7939 (= "Linear Dimension-2")
  dimension "d370" distance P1 P2 = 27.066 (= "Linear Dimension-3")
  dimension "d371" distance P1 P3 = 124 (= "Linear Dimension-4")
  dimension "d372" distance P1 P3 = 27.066 (= "Linear Dimension-5")
  dimension "d373" distance P1 P4 = 124 (= "Linear Dimension-6")
  dimension "d374" distance P1 P4 = 27.066 (= "Linear Dimension-7")
  dimension "d375" = -4 (= "-memberWidth / 2")
extrude "Extrude4" cut sketch "B Facet 45 Triangle 2" profile of L5 L6 L4 against normal blind 4.7 (magnitude of "-( wall + 0.2 mm )")
fillet "Fillet2" radius 1.5 (= "apertureRadius")
work_plane "WorkPlane5" RotateAngle 0 ExtraOffset 0
work_plane "WorkPlane6" AlongDistance 75 (= "bodyWidth / 2") ExtraOffset 0
sketch "B Facet 90 Triangle 1" plane through (0, 0, 75) normal (0, 0, 1) x axis (1, 0, 0)
  line L1 (-36.9655, 27.066) -> (17.1665, -27.066)
  line L2 (-53.4167, -27.066) -> (-36.9655, 27.066)
  line L3 (17.1665, -27.066) -> (-53.4167, -27.066)
  line L4 (-35.0777, 19.5214) -> (7.5097, -23.066)
  line L5 (-48.0205, -23.066) -> (-35.0777, 19.5214)
  line L6 (7.5097, -23.066) -> (-48.0205, -23.066)
  point P1 (0, 0)
  point P2 (17.1665, -27.066)
  point P3 (-36.9655, 27.066)
  point P4 (-53.4167, -27.066)
  dimension "d384" distance P1 P2 = 17.1665 (= "Linear Dimension-2")
  dimension "d385" distance P1 P2 = 27.066 (= "Linear Dimension-3")
  dimension "d386" distance P1 P3 = 36.9655 (= "Linear Dimension-4")
  dimension "d387" distance P1 P3 = 27.066 (= "Linear Dimension-5")
  dimension "d388" distance P1 P4 = 53.4167 (= "Linear Dimension-6")
  dimension "d389" distance P1 P4 = 27.066 (= "Linear Dimension-7")
  dimension "d390" = -4 (= "-memberWidth / 2")
extrude "Extrude5" cut sketch "B Facet 90 Triangle 1" profile of L5 L6 L4 against normal blind 4.7 (magnitude of "-( wall + 0.2 mm )")
sketch "B Facet 90 Triangle 2" plane through (0, 0, 75) normal (0, 0, 1) x axis (1, 0, 0)
  line L1 (-53.4167, -27.066) -> (-36.9655, 27.066)
  line L2 (-124, 27.066) -> (-53.4167, -27.066)
  line L3 (-36.9655, 27.066) -> (-124, 27.066)
  line L4 (-55.5648, -20.3777) -> (-42.3618, 23.066)
  line L5 (-112.2115, 23.066) -> (-55.5648, -20.3777)
  line L6 (-42.3618, 23.066) -> (-112.2115, 23.066)
  point P1 (0, 0)
  point P2 (-36.9655, 27.066)
  point P3 (-53.4167, -27.066)
  point P4 (-124, 27.066)
  dimension "d393" distance P1 P2 = 36.9655 (= "Linear Dimension-2")
  dimension "d394" distance P1 P2 = 27.066 (= "Linear Dimension-3")
  dimension "d395" distance P1 P3 = 53.4167 (= "Linear Dimension-4")
  dimension "d396" distance P1 P3 = 27.066 (= "Linear Dimension-5")
  dimension "d397" distance P1 P4 = 124 (= "Linear Dimension-6")
  dimension "d398" distance P1 P4 = 27.066 (= "Linear Dimension-7")
  dimension "d399" = 4 (= "memberWidth / 2")
extrude "Extrude6" cut sketch "B Facet 90 Triangle 2" profile of L5 L6 L4 against normal blind 4.7 (magnitude of "-( wall + 0.2 mm )")
sketch "B Facet 90 Triangle 3" plane through (0, 0, 75) normal (0, 0, 1) x axis (1, 0, 0)
  line L1 (-124, 27.066) -> (-53.4167, -27.066)
  line L2 (-124, -27.066) -> (-124, 27.066)
  line L3 (-53.4167, -27.066) -> (-124, -27.066)
  line L4 (-120, 18.9574) -> (-65.2053, -23.066)
  line L5 (-120, -23.066) -> (-120, 18.9574)
  line L6 (-65.2053, -23.066) -> (-120, -23.066)
  point P1 (0, 0)
  point P2 (-53.4167, -27.066)
  point P3 (-124, 27.066)
  point P4 (-124, -27.066)
  dimension "d402" distance P1 P2 = 53.4167 (= "Linear Dimension-2")
  dimension "d403" distance P1 P2 = 27.066 (= "Linear Dimension-3")
  dimension "d404" distance P1 P3 = 124 (= "Linear Dimension-4")
  dimension "d405" distance P1 P3 = 27.066 (= "Linear Dimension-5")
  dimension "d406" distance P1 P4 = 124 (= "Linear Dimension-6")
  dimension "d407" distance P1 P4 = 27.066 (= "Linear Dimension-7")
  dimension "d408" = -4 (= "-memberWidth / 2")
extrude "Extrude7" cut sketch "B Facet 90 Triangle 3" profile of L5 L6 L4 against normal blind 4.7 (magnitude of "-( wall + 0.2 mm )")
fillet "Fillet3" radius 1.5 (= "apertureRadius")
work_plane "WorkPlane7" RotateAngle 45 ExtraOffset 0
work_plane "WorkPlane8" AlongDistance 75 (= "bodyWidth / 2") ExtraOffset 0
sketch "B Facet 135 Triangle 1" plane through (0, -53.033, 53.033) normal (0, -0.7071, 0.7071) x axis (1, 0, 0)
  line L1 (62.2721, -27.066) -> (23.9949, 27.066)
  line L2 (-25.3367, 27.066) -> (62.2721, -27.066)
  line L3 (23.9949, 27.066) -> (-25.3367, 27.066)
  line L4 (47.6674, -13.34) -> (21.9244, 23.066)
  line L5 (-11.2532, 23.066) -> (47.6674, -13.34)
  line L6 (21.9244, 23.066) -> (-11.2532, 23.066)
  point P1 (0, 0)
  point P2 (23.9949, 27.066)
  point P3 (62.2721, -27.066)
  point P4 (-25.3367, 27.066)
  dimension "d417" distance P1 P2 = 23.9949 (= "Linear Dimension-2")
  dimension "d418" distance P1 P2 = 27.066 (= "Linear Dimension-3")
  dimension "d419" distance P1 P3 = 62.2721 (= "Linear Dimension-4")
  dimension "d420" distance P1 P3 = 27.066 (= "Linear Dimension-5")
  dimension "d421" distance P1 P4 = 25.3367 (= "Linear Dimension-6")
  dimension "d422" distance P1 P4 = 27.066 (= "Linear Dimension-7")
  dimension "d423" = 4 (= "memberWidth / 2")
extrude "Extrude8" cut sketch "B Facet 135 Triangle 1" profile of L5 L6 L4 against normal blind 4.7 (magnitude of "-( wall + 0.2 mm )")
sketch "B Facet 135 Triangle 2" plane through (0, -53.033, 53.033) normal (0, -0.7071, 0.7071) x axis (1, 0, 0)
  line L1 (-25.3367, 27.066) -> (62.2721, -27.066)
  line L2 (-61.9093, -27.066) -> (-25.3367, 27.066)
  line L3 (62.2721, -27.066) -> (-61.9093, -27.066)
  line L4 (-24.1722, 21.6445) -> (48.1886, -23.066)
  line L5 (-54.3795, -23.066) -> (-24.1722, 21.6445)
  line L6 (48.1886, -23.066) -> (-54.3795, -23.066)
  point P1 (0, 0)
  point P2 (62.2721, -27.066)
  point P3 (-25.3367, 27.066)
  point P4 (-61.9093, -27.066)
  dimension "d426" distance P1 P2 = 62.2721 (= "Linear Dimension-2")
  dimension "d427" distance P1 P2 = 27.066 (= "Linear Dimension-3")
  dimension "d428" distance P1 P3 = 25.3367 (= "Linear Dimension-4")
  dimension "d429" distance P1 P3 = 27.066 (= "Linear Dimension-5")
  dimension "d430" distance P1 P4 = 61.9093 (= "Linear Dimension-6")
  dimension "d431" distance P1 P4 = 27.066 (= "Linear Dimension-7")
  dimension "d432" = -4 (= "-memberWidth / 2")
extrude "Extrude9" cut sketch "B Facet 135 Triangle 2" profile of L5 L6 L4 against normal blind 4.7 (magnitude of "-( wall + 0.2 mm )")
sketch "B Facet 135 Triangle 3" plane through (0, -53.033, 53.033) normal (0, -0.7071, 0.7071) x axis (1, 0, 0)
  line L1 (-61.9093, -27.066) -> (-25.3367, 27.066)
  line L2 (-124, 27.066) -> (-61.9093, -27.066)
  line L3 (-25.3367, 27.066) -> (-124, 27.066)
  line L4 (-62.6909, -21.0779) -> (-32.8665, 23.066)
  line L5 (-113.325, 23.066) -> (-62.6909, -21.0779)
  line L6 (-32.8665, 23.066) -> (-113.325, 23.066)
  point P1 (0, 0)
  point P2 (-25.3367, 27.066)
  point P3 (-61.9093, -27.066)
  point P4 (-124, 27.066)
  dimension "d435" distance P1 P2 = 25.3367 (= "Linear Dimension-2")
  dimension "d436" distance P1 P2 = 27.066 (= "Linear Dimension-3")
  dimension "d437" distance P1 P3 = 61.9093 (= "Linear Dimension-4")
  dimension "d438" distance P1 P3 = 27.066 (= "Linear Dimension-5")
  dimension "d439" distance P1 P4 = 124 (= "Linear Dimension-6")
  dimension "d440" distance P1 P4 = 27.066 (= "Linear Dimension-7")
  dimension "d441" = 4 (= "memberWidth / 2")
extrude "Extrude10" cut sketch "B Facet 135 Triangle 3" profile of L5 L6 L4 against normal blind 4.7 (magnitude of "-( wall + 0.2 mm )")
sketch "B Facet 135 Triangle 4" plane through (0, -53.033, 53.033) normal (0, -0.7071, 0.7071) x axis (1, 0, 0)
  line L1 (-124, 27.066) -> (-61.9093, -27.066)
  line L2 (-124, -27.066) -> (-124, 27.066)
  line L3 (-61.9093, -27.066) -> (-124, -27.066)
  line L4 (-120, 18.272) -> (-72.5843, -23.066)
  line L5 (-120, -23.066) -> (-120, 18.272)
  line L6 (-72.5843, -23.066) -> (-120, -23.066)
  point P1 (0, 0)
  point P2 (-61.9093, -27.066)
  point P3 (-124, 27.066)
  point P4 (-124, -27.066)
  dimension "d444" distance P1 P2 = 61.9093 (= "Linear Dimension-2")
  dimension "d445" distance P1 P2 = 27.066 (= "Linear Dimension-3")
  dimension "d446" distance P1 P3 = 124 (= "Linear Dimension-4")
  dimension "d447" distance P1 P3 = 27.066 (= "Linear Dimension-5")
  dimension "d448" distance P1 P4 = 124 (= "Linear Dimension-6")
  dimension "d449" distance P1 P4 = 27.066 (= "Linear Dimension-7")
  dimension "d450" = -4 (= "-memberWidth / 2")
extrude "Extrude11" cut sketch "B Facet 135 Triangle 4" profile of L5 L6 L4 against normal blind 4.7 (magnitude of "-( wall + 0.2 mm )")
fillet "Fillet4" radius 1.5 (= "apertureRadius")
work_plane "WorkPlane9" RotateAngle 90 ExtraOffset 0
work_plane "WorkPlane10" AlongDistance 75 (= "bodyWidth / 2") ExtraOffset 0
sketch "B Facet 180 Triangle 1" plane through (0, -75, 0) normal (0, -1, 0) x axis (-1, 0, 0)
  line L1 (-65.1005, 27.066) -> (-65.1005, -27.066)
  line L2 (-2.067, -27.066) -> (-65.1005, 27.066)
  line L3 (-65.1005, -27.066) -> (-2.067, -27.066)
  line L4 (-61.1005, 18.3583) -> (-61.1005, -23.066)
  line L5 (-12.8644, -23.066) -> (-61.1005, 18.3583)
  line L6 (-61.1005, -23.066) -> (-12.8644, -23.066)
  point P1 (0, 0)
  point P2 (-65.1005, -27.066)
  point P3 (-65.1005, 27.066)
  point P4 (-2.067, -27.066)
  dimension "d459" distance P1 P2 = 65.1005 (= "Linear Dimension-2")
  dimension "d460" distance P1 P2 = 27.066 (= "Linear Dimension-3")
  dimension "d461" distance P1 P3 = 65.1005 (= "Linear Dimension-4")
  dimension "d462" distance P1 P3 = 27.066 (= "Linear Dimension-5")
  dimension "d463" distance P1 P4 = 2.067 (= "Linear Dimension-6")
  dimension "d464" distance P1 P4 = 27.066 (= "Linear Dimension-7")
  dimension "d465" = 4 (= "memberWidth / 2")
extrude "Extrude12" cut sketch "B Facet 180 Triangle 1" profile of L5 L6 L4 against normal blind 4.7 (magnitude of "-( wall + 0.2 mm )")
sketch "B Facet 180 Triangle 2" plane through (0, -75, 0) normal (0, -1, 0) x axis (-1, 0, 0)
  line L1 (-2.067, -27.066) -> (-65.1005, 27.066)
  line L2 (60.9665, 27.066) -> (-2.067, -27.066)
  line L3 (-65.1005, 27.066) -> (60.9665, 27.066)
  line L4 (-2.067, -21.7934) -> (-54.3031, 23.066)
  line L5 (50.1691, 23.066) -> (-2.067, -21.7934)
  line L6 (-54.3031, 23.066) -> (50.1691, 23.066)
  point P1 (0, 0)
  point P2 (-65.1005, 27.066)
  point P3 (-2.067, -27.066)
  point P4 (60.9665, 27.066)
  dimension "d468" distance P1 P2 = 65.1005 (= "Linear Dimension-2")
  dimension "d469" distance P1 P2 = 27.066 (= "Linear Dimension-3")
  dimension "d470" distance P1 P3 = 2.067 (= "Linear Dimension-4")
  dimension "d471" distance P1 P3 = 27.066 (= "Linear Dimension-5")
  dimension "d472" distance P1 P4 = 60.9665 (= "Linear Dimension-6")
  dimension "d473" distance P1 P4 = 27.066 (= "Linear Dimension-7")
  dimension "d474" = -4 (= "-memberWidth / 2")
extrude "Extrude13" cut sketch "B Facet 180 Triangle 2" profile of L5 L6 L4 against normal blind 4.7 (magnitude of "-( wall + 0.2 mm )")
